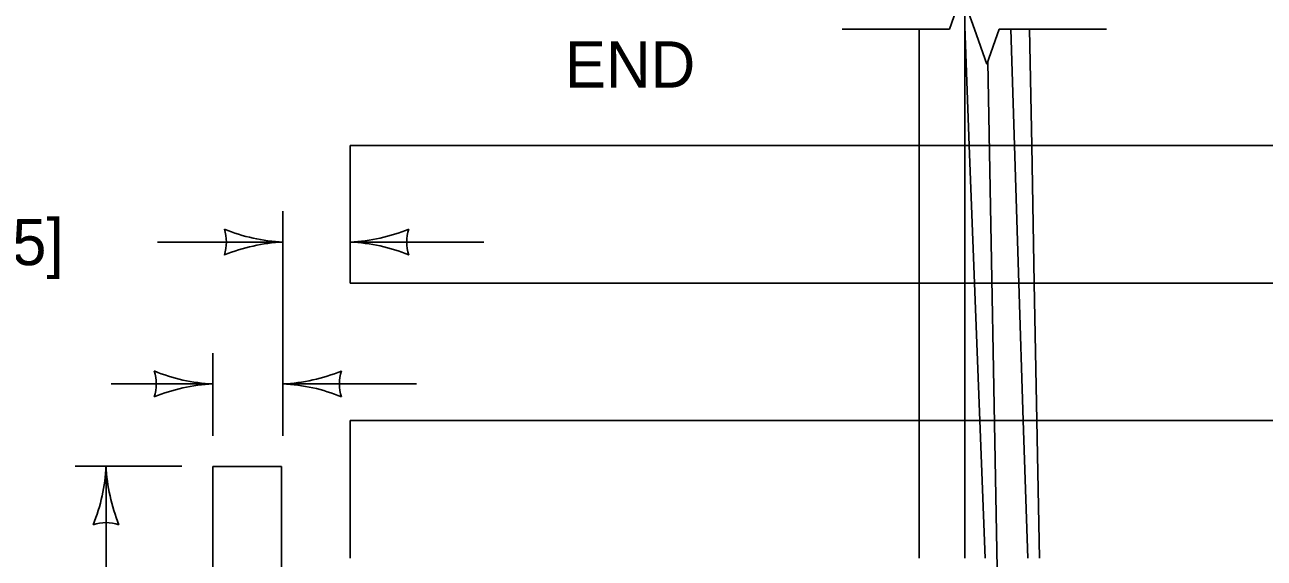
# Model space of a CAD drawing. Extents: x 49991.4 to 50021, y 49987.6 to 50011.4.
# Drawn here: x 50008.713 to 50010.323, y 49997.286 to 49997.978 of the extents above; entities that cross this region are included whole.
import ezdxf

# ---------------------------------------------------------------- set-up
doc = ezdxf.new("R2010")
doc.units = 0
for name, color, linetype in [('Level 1', 7, 'Continuous'), ('Level 2', 7, 'Continuous'), ('Level 3', 7, 'Continuous'), ('Level 4', 7, 'Continuous'), ('Level 6', 7, 'Continuous')]:
    doc.layers.add(name, color=color, linetype=linetype)

msp = doc.modelspace()

# ---------------------------------------------------------------- linework, layer by layer
at = {"layer": 'Level 1'}
for p, q in [((50009.9345, 49997.821), (50009.9345, 49998.0065)), ((50009.875, 49997.9721), (50009.875, 49997.821)), ((50009.9401, 49997.821), (50009.9345, 49997.9755)), ((50009.994, 49997.9721), (50009.9987, 49997.821)), ((50010.0213, 49997.821), (50010.0184, 49997.9721)), ((50009.1361, 49997.821), (50009.1361, 49997.6425)), ((50009.1361, 49997.821), (50012.7152, 49997.821)), ((50009.1361, 49997.6425), (50012.9702, 49997.6425)), ((50009.875, 49997.6425), (50009.875, 49997.464)), ((50009.9345, 49997.464), (50009.9345, 49997.6425)), ((50009.9538, 49997.464), (50009.947, 49997.6425)), ((50010.0043, 49997.6425), (50010.01, 49997.464)), ((50010.0279, 49997.464), (50010.0246, 49997.6425)), ((50009.1361, 49997.464), (50009.1361, 49997.2855)), ((50009.1361, 49997.464), (50013.2251, 49997.464)), ((50009.0467, 49997.4044), (50008.9574, 49997.4044)), ((50008.9574, 49997.4044), (50008.9574, 49995.084)), ((50009.0467, 49997.4044), (50009.0467, 49995.084))]:
    msp.add_line(p, q, dxfattribs=at)
at = {"layer": 'Level 3'}
for p, q in [((50009.0486, 49997.7357), (50009.0486, 49997.4444)), ((50009.0486, 49997.6957), (50008.8856, 49997.6957)), ((50009.3095, 49997.6957), (50009.1361, 49997.6957)), ((50008.9574, 49997.5516), (50008.9574, 49997.4444)), ((50008.9574, 49997.5116), (50008.8253, 49997.5116)), ((50009.222, 49997.5116), (50009.0486, 49997.5116)), ((50008.9174, 49997.405), (50008.7788, 49997.405)), ((50008.8188, 49996.155), (50008.8188, 49997.405))]:
    msp.add_line(p, q, dxfattribs=at)
for centre, radius, start, end in [((50009.0578, 49997.9178), 0.2223, 247.456, 267.6395), ((50008.9204, 49997.6957), 0.0548, 342.1388, 17.8612), ((50009.1246, 49997.9284), 0.233, 272.8273, 292.0772), ((50009.2643, 49997.6957), 0.0548, 162.1388, 197.8612), ((50009.0601, 49997.463), 0.233, 92.8273, 112.0772), ((50009.1269, 49997.4736), 0.2223, 67.456, 87.6395), ((50008.9666, 49997.7337), 0.2223, 247.456, 267.6395), ((50008.8292, 49997.5116), 0.0548, 342.1388, 17.8612), ((50009.0371, 49997.7443), 0.233, 272.8273, 292.0772), ((50009.1768, 49997.5116), 0.0548, 162.1388, 197.8612), ((50008.9689, 49997.2789), 0.233, 92.8273, 112.0772), ((50009.0394, 49997.2895), 0.2223, 67.456, 87.6395), ((50008.5967, 49997.4142), 0.2223, 337.456, 357.6395), ((50009.0515, 49997.4165), 0.233, 182.8273, 202.0772), ((50008.8188, 49997.2768), 0.0548, 72.1388, 107.8612)]:
    msp.add_arc(centre, radius, start, end, dxfattribs=at)
at = {"layer": 'Level 4'}
for p, q in [((50009.964, 49997.9295), (50009.994, 49996.3335)), ((50009.875, 49997.821), (50009.875, 49997.6425)), ((50009.9345, 49997.6425), (50009.9345, 49997.821)), ((50009.947, 49997.6425), (50009.9401, 49997.821)), ((50009.9987, 49997.821), (50010.0043, 49997.6425)), ((50010.0246, 49997.6425), (50010.0213, 49997.821)), ((50009.875, 49997.464), (50009.875, 49997.2855)), ((50009.9345, 49997.2855), (50009.9345, 49997.464)), ((50009.9609, 49997.2855), (50009.9538, 49997.464)), ((50010.01, 49997.464), (50010.016, 49997.2855)), ((50010.0315, 49997.2855), (50010.0279, 49997.464))]:
    msp.add_line(p, q, dxfattribs=at)
at = {"layer": 'Level 6'}
for p, q in [((50009.9305, 49998.0178), (50009.9143, 49997.9721)), ((50009.9305, 49998.0178), (50009.9467, 49997.9721)), ((50009.775, 49997.9721), (50009.9143, 49997.9721)), ((50009.9467, 49997.9721), (50009.9629, 49997.9264)), ((50009.9791, 49997.9721), (50009.9629, 49997.9264)), ((50009.9791, 49997.9721), (50010.1184, 49997.9721))]:
    msp.add_line(p, q, dxfattribs=at)

# ---------------------------------------------------------------- texts
at = {"layer": 'Level 2'}
for s, p in [('END', (50009.4148, 49997.8961)), ('3" [75]', (50008.5345, 49997.6657))]:
    msp.add_text(s, height=0.06, dxfattribs=at).set_placement(p)

doc.saveas('drawing.dxf')
